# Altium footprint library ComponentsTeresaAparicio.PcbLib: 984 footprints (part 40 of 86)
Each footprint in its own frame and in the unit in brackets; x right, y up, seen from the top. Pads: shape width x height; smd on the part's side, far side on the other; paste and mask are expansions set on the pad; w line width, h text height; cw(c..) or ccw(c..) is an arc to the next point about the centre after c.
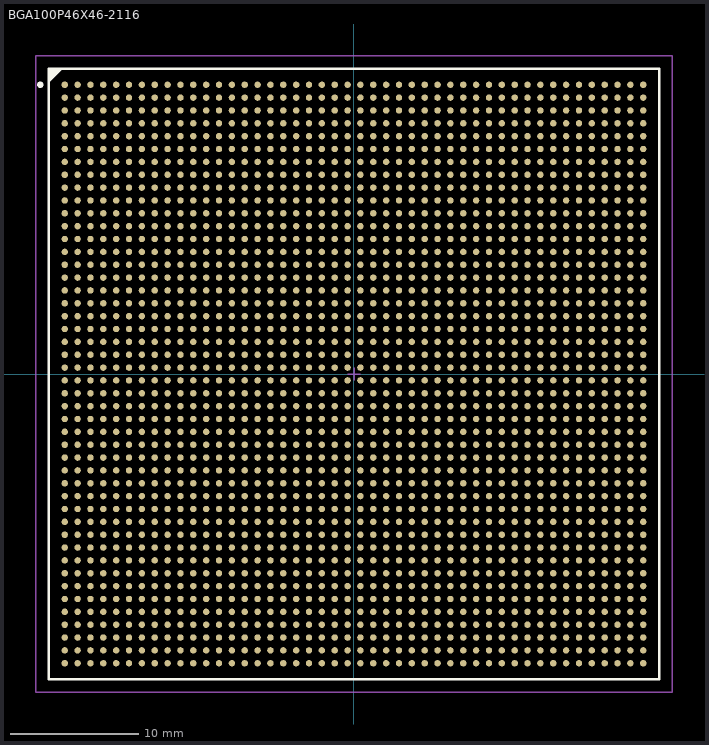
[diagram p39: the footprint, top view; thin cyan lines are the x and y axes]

## BGA100P46X46-2116 [mm] "BGA, 2116-Leads, Body 47.5x47.5mm, Pitch 1mm"
height 3.5
pads (2116):
  round 0.5 smd: A1(-22.5,22.5) A2(-21.5,22.5) A3(-20.5,22.5) A4(-19.5,22.5) A5(-18.5,22.5) A6(-17.5,22.5) A7(-16.5,22.5) A8(-15.5,22.5) A9(-14.5,22.5) A10(-13.5,22.5) A11(-12.5,22.5) A12(-11.5,22.5) A13(-10.5,22.5) A14(-9.5,22.5) A15(-8.5,22.5) A16(-7.5,22.5) A17(-6.5,22.5) A18(-5.5,22.5) A19(-4.5,22.5) A20(-3.5,22.5) A21(-2.5,22.5) A22(-1.5,22.5) A23(-0.5,22.5) A24(0.5,22.5) A25(1.5,22.5) A26(2.5,22.5) A27(3.5,22.5) A28(4.5,22.5) A29(5.5,22.5) A30(6.5,22.5) A31(7.5,22.5) A32(8.5,22.5) A33(9.5,22.5) A34(10.5,22.5) A35(11.5,22.5) A36(12.5,22.5) A37(13.5,22.5) A38(14.5,22.5) A39(15.5,22.5) A40(16.5,22.5) A41(17.5,22.5) A42(18.5,22.5) A43(19.5,22.5) A44(20.5,22.5) A45(21.5,22.5) A46(22.5,22.5) AA1(-22.5,2.5) AA2(-21.5,2.5) AA3(-20.5,2.5) AA4(-19.5,2.5) AA5(-18.5,2.5) AA6(-17.5,2.5) AA7(-16.5,2.5) AA8(-15.5,2.5) AA9(-14.5,2.5) AA10(-13.5,2.5) AA11(-12.5,2.5) AA12(-11.5,2.5) AA13(-10.5,2.5) AA14(-9.5,2.5) AA15(-8.5,2.5) AA16(-7.5,2.5) AA17(-6.5,2.5) AA18(-5.5,2.5) AA19(-4.5,2.5) AA20(-3.5,2.5) AA21(-2.5,2.5) AA22(-1.5,2.5) AA23(-0.5,2.5) AA24(0.5,2.5) AA25(1.5,2.5) AA26(2.5,2.5) AA27(3.5,2.5) AA28(4.5,2.5) AA29(5.5,2.5) AA30(6.5,2.5) AA31(7.5,2.5) AA32(8.5,2.5) AA33(9.5,2.5) AA34(10.5,2.5) AA35(11.5,2.5) AA36(12.5,2.5) AA37(13.5,2.5) AA38(14.5,2.5) AA39(15.5,2.5) AA40(16.5,2.5) AA41(17.5,2.5) AA42(18.5,2.5) AA43(19.5,2.5) AA44(20.5,2.5) AA45(21.5,2.5) AA46(22.5,2.5) AB1(-22.5,1.5) AB2(-21.5,1.5) AB3(-20.5,1.5) AB4(-19.5,1.5) AB5(-18.5,1.5) AB6(-17.5,1.5) AB7(-16.5,1.5) AB8(-15.5,1.5) AB9(-14.5,1.5) AB10(-13.5,1.5) AB11(-12.5,1.5) AB12(-11.5,1.5) AB13(-10.5,1.5) AB14(-9.5,1.5) AB15(-8.5,1.5) AB16(-7.5,1.5) AB17(-6.5,1.5) AB18(-5.5,1.5) AB19(-4.5,1.5) AB20(-3.5,1.5) AB21(-2.5,1.5) AB22(-1.5,1.5) AB23(-0.5,1.5) AB24(0.5,1.5) AB25(1.5,1.5) AB26(2.5,1.5) AB27(3.5,1.5) AB28(4.5,1.5) AB29(5.5,1.5) AB30(6.5,1.5) AB31(7.5,1.5) AB32(8.5,1.5) AB33(9.5,1.5) AB34(10.5,1.5) AB35(11.5,1.5) AB36(12.5,1.5) AB37(13.5,1.5) AB38(14.5,1.5) AB39(15.5,1.5) AB40(16.5,1.5) AB41(17.5,1.5) AB42(18.5,1.5) AB43(19.5,1.5) AB44(20.5,1.5) AB45(21.5,1.5) AB46(22.5,1.5) AC1(-22.5,0.5) AC2(-21.5,0.5) AC3(-20.5,0.5) AC4(-19.5,0.5) AC5(-18.5,0.5) AC6(-17.5,0.5) AC7(-16.5,0.5) AC8(-15.5,0.5) AC9(-14.5,0.5) AC10(-13.5,0.5) AC11(-12.5,0.5) AC12(-11.5,0.5) AC13(-10.5,0.5) AC14(-9.5,0.5) AC15(-8.5,0.5) AC16(-7.5,0.5) AC17(-6.5,0.5) AC18(-5.5,0.5) AC19(-4.5,0.5) AC20(-3.5,0.5) AC21(-2.5,0.5) AC22(-1.5,0.5) AC23(-0.5,0.5) AC24(0.5,0.5) AC25(1.5,0.5) AC26(2.5,0.5) AC27(3.5,0.5) AC28(4.5,0.5) AC29(5.5,0.5) AC30(6.5,0.5) AC31(7.5,0.5) AC32(8.5,0.5) AC33(9.5,0.5) AC34(10.5,0.5) AC35(11.5,0.5) AC36(12.5,0.5) AC37(13.5,0.5) AC38(14.5,0.5) AC39(15.5,0.5) AC40(16.5,0.5) AC41(17.5,0.5) AC42(18.5,0.5) AC43(19.5,0.5) AC44(20.5,0.5) AC45(21.5,0.5) AC46(22.5,0.5) AD1(-22.5,-0.5) AD2(-21.5,-0.5) AD3(-20.5,-0.5) AD4(-19.5,-0.5) AD5(-18.5,-0.5) AD6(-17.5,-0.5) AD7(-16.5,-0.5) AD8(-15.5,-0.5) AD9(-14.5,-0.5) AD10(-13.5,-0.5) AD11(-12.5,-0.5) AD12(-11.5,-0.5) AD13(-10.5,-0.5) AD14(-9.5,-0.5) AD15(-8.5,-0.5) AD16(-7.5,-0.5) AD17(-6.5,-0.5) AD18(-5.5,-0.5) AD19(-4.5,-0.5) AD20(-3.5,-0.5) AD21(-2.5,-0.5) AD22(-1.5,-0.5) AD23(-0.5,-0.5) AD24(0.5,-0.5) AD25(1.5,-0.5) AD26(2.5,-0.5) AD27(3.5,-0.5) AD28(4.5,-0.5) AD29(5.5,-0.5) AD30(6.5,-0.5) AD31(7.5,-0.5) AD32(8.5,-0.5) AD33(9.5,-0.5) AD34(10.5,-0.5) AD35(11.5,-0.5) AD36(12.5,-0.5) AD37(13.5,-0.5) AD38(14.5,-0.5) AD39(15.5,-0.5) AD40(16.5,-0.5) AD41(17.5,-0.5) AD42(18.5,-0.5) AD43(19.5,-0.5) AD44(20.5,-0.5) AD45(21.5,-0.5) AD46(22.5,-0.5) AE1(-22.5,-1.5) AE2(-21.5,-1.5) AE3(-20.5,-1.5) AE4(-19.5,-1.5) AE5(-18.5,-1.5) AE6(-17.5,-1.5) AE7(-16.5,-1.5) AE8(-15.5,-1.5) AE9(-14.5,-1.5) AE10(-13.5,-1.5) AE11(-12.5,-1.5) AE12(-11.5,-1.5) AE13(-10.5,-1.5) AE14(-9.5,-1.5) AE15(-8.5,-1.5) AE16(-7.5,-1.5) AE17(-6.5,-1.5) AE18(-5.5,-1.5) AE19(-4.5,-1.5) AE20(-3.5,-1.5) AE21(-2.5,-1.5) AE22(-1.5,-1.5) AE23(-0.5,-1.5) AE24(0.5,-1.5) AE25(1.5,-1.5) AE26(2.5,-1.5) AE27(3.5,-1.5) AE28(4.5,-1.5) AE29(5.5,-1.5) AE30(6.5,-1.5) AE31(7.5,-1.5) AE32(8.5,-1.5) AE33(9.5,-1.5) AE34(10.5,-1.5) AE35(11.5,-1.5) AE36(12.5,-1.5) AE37(13.5,-1.5) AE38(14.5,-1.5) AE39(15.5,-1.5) AE40(16.5,-1.5) AE41(17.5,-1.5) AE42(18.5,-1.5) AE43(19.5,-1.5) AE44(20.5,-1.5) AE45(21.5,-1.5) AE46(22.5,-1.5) AF1(-22.5,-2.5) AF2(-21.5,-2.5) AF3(-20.5,-2.5) AF4(-19.5,-2.5) AF5(-18.5,-2.5) AF6(-17.5,-2.5) AF7(-16.5,-2.5) AF8(-15.5,-2.5) AF9(-14.5,-2.5) AF10(-13.5,-2.5) AF11(-12.5,-2.5) AF12(-11.5,-2.5) AF13(-10.5,-2.5) AF14(-9.5,-2.5) AF15(-8.5,-2.5) AF16(-7.5,-2.5) AF17(-6.5,-2.5) AF18(-5.5,-2.5) AF19(-4.5,-2.5) AF20(-3.5,-2.5) AF21(-2.5,-2.5) AF22(-1.5,-2.5) AF23(-0.5,-2.5) AF24(0.5,-2.5) AF25(1.5,-2.5) AF26(2.5,-2.5) AF27(3.5,-2.5) AF28(4.5,-2.5) AF29(5.5,-2.5) AF30(6.5,-2.5) AF31(7.5,-2.5) AF32(8.5,-2.5) AF33(9.5,-2.5) AF34(10.5,-2.5) AF35(11.5,-2.5) AF36(12.5,-2.5) AF37(13.5,-2.5) AF38(14.5,-2.5) AF39(15.5,-2.5) AF40(16.5,-2.5) AF41(17.5,-2.5) AF42(18.5,-2.5) AF43(19.5,-2.5) AF44(20.5,-2.5) AF45(21.5,-2.5) AF46(22.5,-2.5) AG1(-22.5,-3.5) AG2(-21.5,-3.5) AG3(-20.5,-3.5) AG4(-19.5,-3.5) AG5(-18.5,-3.5) AG6(-17.5,-3.5) AG7(-16.5,-3.5) AG8(-15.5,-3.5) AG9(-14.5,-3.5) AG10(-13.5,-3.5) AG11(-12.5,-3.5) AG12(-11.5,-3.5) AG13(-10.5,-3.5) AG14(-9.5,-3.5) AG15(-8.5,-3.5) AG16(-7.5,-3.5) AG17(-6.5,-3.5) AG18(-5.5,-3.5) AG19(-4.5,-3.5) AG20(-3.5,-3.5) AG21(-2.5,-3.5) AG22(-1.5,-3.5) AG23(-0.5,-3.5) AG24(0.5,-3.5) AG25(1.5,-3.5) AG26(2.5,-3.5) AG27(3.5,-3.5) AG28(4.5,-3.5) AG29(5.5,-3.5) AG30(6.5,-3.5) AG31(7.5,-3.5) AG32(8.5,-3.5) AG33(9.5,-3.5) AG34(10.5,-3.5) AG35(11.5,-3.5) AG36(12.5,-3.5) AG37(13.5,-3.5) AG38(14.5,-3.5) AG39(15.5,-3.5) AG40(16.5,-3.5) AG41(17.5,-3.5) AG42(18.5,-3.5) AG43(19.5,-3.5) AG44(20.5,-3.5) AG45(21.5,-3.5) AG46(22.5,-3.5) AH1(-22.5,-4.5) AH2(-21.5,-4.5) AH3(-20.5,-4.5) AH4(-19.5,-4.5) AH5(-18.5,-4.5) AH6(-17.5,-4.5) AH7(-16.5,-4.5) AH8(-15.5,-4.5) AH9(-14.5,-4.5) AH10(-13.5,-4.5) AH11(-12.5,-4.5) AH12(-11.5,-4.5) AH13(-10.5,-4.5) AH14(-9.5,-4.5) AH15(-8.5,-4.5) AH16(-7.5,-4.5) AH17(-6.5,-4.5) AH18(-5.5,-4.5) AH19(-4.5,-4.5) AH20(-3.5,-4.5) AH21(-2.5,-4.5) AH22(-1.5,-4.5) AH23(-0.5,-4.5) AH24(0.5,-4.5) AH25(1.5,-4.5) AH26(2.5,-4.5) AH27(3.5,-4.5) AH28(4.5,-4.5) AH29(5.5,-4.5) AH30(6.5,-4.5) AH31(7.5,-4.5) AH32(8.5,-4.5) AH33(9.5,-4.5) AH34(10.5,-4.5) AH35(11.5,-4.5) AH36(12.5,-4.5) AH37(13.5,-4.5) AH38(14.5,-4.5) AH39(15.5,-4.5) AH40(16.5,-4.5) AH41(17.5,-4.5) AH42(18.5,-4.5) AH43(19.5,-4.5) AH44(20.5,-4.5) AH45(21.5,-4.5) AH46(22.5,-4.5) AJ1(-22.5,-5.5) AJ2(-21.5,-5.5) AJ3(-20.5,-5.5) AJ4(-19.5,-5.5) AJ5(-18.5,-5.5) AJ6(-17.5,-5.5) AJ7(-16.5,-5.5) AJ8(-15.5,-5.5) AJ9(-14.5,-5.5) AJ10(-13.5,-5.5) AJ11(-12.5,-5.5) AJ12(-11.5,-5.5) AJ13(-10.5,-5.5) AJ14(-9.5,-5.5) AJ15(-8.5,-5.5) AJ16(-7.5,-5.5) AJ17(-6.5,-5.5) AJ18(-5.5,-5.5) AJ19(-4.5,-5.5) AJ20(-3.5,-5.5) AJ21(-2.5,-5.5) AJ22(-1.5,-5.5) AJ23(-0.5,-5.5) AJ24(0.5,-5.5) AJ25(1.5,-5.5) AJ26(2.5,-5.5) AJ27(3.5,-5.5) AJ28(4.5,-5.5) AJ29(5.5,-5.5) AJ30(6.5,-5.5) AJ31(7.5,-5.5) AJ32(8.5,-5.5) AJ33(9.5,-5.5) AJ34(10.5,-5.5) AJ35(11.5,-5.5) AJ36(12.5,-5.5) AJ37(13.5,-5.5) AJ38(14.5,-5.5) AJ39(15.5,-5.5) AJ40(16.5,-5.5) AJ41(17.5,-5.5) AJ42(18.5,-5.5) AJ43(19.5,-5.5) AJ44(20.5,-5.5) AJ45(21.5,-5.5) AJ46(22.5,-5.5) AK1(-22.5,-6.5) AK2(-21.5,-6.5) AK3(-20.5,-6.5) AK4(-19.5,-6.5) AK5(-18.5,-6.5) AK6(-17.5,-6.5) AK7(-16.5,-6.5) AK8(-15.5,-6.5) AK9(-14.5,-6.5) AK10(-13.5,-6.5) AK11(-12.5,-6.5) AK12(-11.5,-6.5) AK13(-10.5,-6.5) AK14(-9.5,-6.5) AK15(-8.5,-6.5) AK16(-7.5,-6.5) AK17(-6.5,-6.5) AK18(-5.5,-6.5) AK19(-4.5,-6.5) AK20(-3.5,-6.5) AK21(-2.5,-6.5) AK22(-1.5,-6.5) AK23(-0.5,-6.5) AK24(0.5,-6.5) AK25(1.5,-6.5) AK26(2.5,-6.5) AK27(3.5,-6.5) AK28(4.5,-6.5) AK29(5.5,-6.5) AK30(6.5,-6.5) AK31(7.5,-6.5) AK32(8.5,-6.5) AK33(9.5,-6.5) AK34(10.5,-6.5) AK35(11.5,-6.5) AK36(12.5,-6.5) AK37(13.5,-6.5) AK38(14.5,-6.5) AK39(15.5,-6.5) AK40(16.5,-6.5) AK41(17.5,-6.5) AK42(18.5,-6.5) AK43(19.5,-6.5) AK44(20.5,-6.5) AK45(21.5,-6.5) AK46(22.5,-6.5) AL1(-22.5,-7.5) AL2(-21.5,-7.5) AL3(-20.5,-7.5) AL4(-19.5,-7.5) AL5(-18.5,-7.5) AL6(-17.5,-7.5) AL7(-16.5,-7.5) AL8(-15.5,-7.5) AL9(-14.5,-7.5) AL10(-13.5,-7.5) AL11(-12.5,-7.5) AL12(-11.5,-7.5) AL13(-10.5,-7.5) AL14(-9.5,-7.5) AL15(-8.5,-7.5) AL16(-7.5,-7.5) AL17(-6.5,-7.5) AL18(-5.5,-7.5) AL19(-4.5,-7.5) AL20(-3.5,-7.5) AL21(-2.5,-7.5) AL22(-1.5,-7.5) AL23(-0.5,-7.5) AL24(0.5,-7.5) AL25(1.5,-7.5) AL26(2.5,-7.5) AL27(3.5,-7.5) AL28(4.5,-7.5) AL29(5.5,-7.5) AL30(6.5,-7.5) AL31(7.5,-7.5) AL32(8.5,-7.5) AL33(9.5,-7.5) AL34(10.5,-7.5) AL35(11.5,-7.5) AL36(12.5,-7.5) AL37(13.5,-7.5) AL38(14.5,-7.5) AL39(15.5,-7.5) AL40(16.5,-7.5) AL41(17.5,-7.5) AL42(18.5,-7.5) AL43(19.5,-7.5) AL44(20.5,-7.5) AL45(21.5,-7.5) AL46(22.5,-7.5) AM1(-22.5,-8.5) AM2(-21.5,-8.5) AM3(-20.5,-8.5) AM4(-19.5,-8.5) AM5(-18.5,-8.5) AM6(-17.5,-8.5) AM7(-16.5,-8.5) AM8(-15.5,-8.5) AM9(-14.5,-8.5) AM10(-13.5,-8.5) AM11(-12.5,-8.5) AM12(-11.5,-8.5) AM13(-10.5,-8.5) AM14(-9.5,-8.5) AM15(-8.5,-8.5) AM16(-7.5,-8.5) AM17(-6.5,-8.5) AM18(-5.5,-8.5) AM19(-4.5,-8.5) AM20(-3.5,-8.5) AM21(-2.5,-8.5) AM22(-1.5,-8.5) AM23(-0.5,-8.5) AM24(0.5,-8.5) AM25(1.5,-8.5) AM26(2.5,-8.5) AM27(3.5,-8.5) AM28(4.5,-8.5) AM29(5.5,-8.5) AM30(6.5,-8.5) AM31(7.5,-8.5) AM32(8.5,-8.5) AM33(9.5,-8.5) AM34(10.5,-8.5) AM35(11.5,-8.5) AM36(12.5,-8.5) AM37(13.5,-8.5) AM38(14.5,-8.5) AM39(15.5,-8.5) AM40(16.5,-8.5) AM41(17.5,-8.5) AM42(18.5,-8.5) AM43(19.5,-8.5) AM44(20.5,-8.5) AM45(21.5,-8.5) AM46(22.5,-8.5) AN1(-22.5,-9.5) AN2(-21.5,-9.5) AN3(-20.5,-9.5) AN4(-19.5,-9.5) AN5(-18.5,-9.5) AN6(-17.5,-9.5) AN7(-16.5,-9.5) AN8(-15.5,-9.5) AN9(-14.5,-9.5) AN10(-13.5,-9.5) AN11(-12.5,-9.5) AN12(-11.5,-9.5) AN13(-10.5,-9.5) AN14(-9.5,-9.5) AN15(-8.5,-9.5) AN16(-7.5,-9.5) AN17(-6.5,-9.5) AN18(-5.5,-9.5) AN19(-4.5,-9.5) AN20(-3.5,-9.5) AN21(-2.5,-9.5) AN22(-1.5,-9.5) AN23(-0.5,-9.5) AN24(0.5,-9.5) AN25(1.5,-9.5) AN26(2.5,-9.5) AN27(3.5,-9.5) AN28(4.5,-9.5) AN29(5.5,-9.5) AN30(6.5,-9.5) AN31(7.5,-9.5) AN32(8.5,-9.5) AN33(9.5,-9.5) AN34(10.5,-9.5) AN35(11.5,-9.5) AN36(12.5,-9.5) AN37(13.5,-9.5) AN38(14.5,-9.5) AN39(15.5,-9.5) AN40(16.5,-9.5) AN41(17.5,-9.5) AN42(18.5,-9.5) AN43(19.5,-9.5) AN44(20.5,-9.5) AN45(21.5,-9.5) AN46(22.5,-9.5) AP1(-22.5,-10.5) AP2(-21.5,-10.5) AP3(-20.5,-10.5) AP4(-19.5,-10.5) AP5(-18.5,-10.5) AP6(-17.5,-10.5) AP7(-16.5,-10.5) AP8(-15.5,-10.5) AP9(-14.5,-10.5) AP10(-13.5,-10.5) AP11(-12.5,-10.5) AP12(-11.5,-10.5) AP13(-10.5,-10.5) AP14(-9.5,-10.5) AP15(-8.5,-10.5) AP16(-7.5,-10.5) AP17(-6.5,-10.5) AP18(-5.5,-10.5) AP19(-4.5,-10.5) AP20(-3.5,-10.5) AP21(-2.5,-10.5) AP22(-1.5,-10.5) AP23(-0.5,-10.5) AP24(0.5,-10.5) AP25(1.5,-10.5) AP26(2.5,-10.5) AP27(3.5,-10.5) AP28(4.5,-10.5) AP29(5.5,-10.5) AP30(6.5,-10.5) AP31(7.5,-10.5) AP32(8.5,-10.5) AP33(9.5,-10.5) AP34(10.5,-10.5) AP35(11.5,-10.5) AP36(12.5,-10.5) AP37(13.5,-10.5) AP38(14.5,-10.5) AP39(15.5,-10.5) AP40(16.5,-10.5) AP41(17.5,-10.5) AP42(18.5,-10.5) AP43(19.5,-10.5) AP44(20.5,-10.5) AP45(21.5,-10.5) AP46(22.5,-10.5) AR1(-22.5,-11.5) AR2(-21.5,-11.5) AR3(-20.5,-11.5) AR4(-19.5,-11.5) AR5(-18.5,-11.5) AR6(-17.5,-11.5) AR7(-16.5,-11.5) AR8(-15.5,-11.5) AR9(-14.5,-11.5) AR10(-13.5,-11.5) AR11(-12.5,-11.5) AR12(-11.5,-11.5) AR13(-10.5,-11.5) AR14(-9.5,-11.5) AR15(-8.5,-11.5) AR16(-7.5,-11.5) AR17(-6.5,-11.5) AR18(-5.5,-11.5) AR19(-4.5,-11.5) AR20(-3.5,-11.5) AR21(-2.5,-11.5) AR22(-1.5,-11.5) AR23(-0.5,-11.5) AR24(0.5,-11.5) AR25(1.5,-11.5) AR26(2.5,-11.5) AR27(3.5,-11.5) AR28(4.5,-11.5) AR29(5.5,-11.5) AR30(6.5,-11.5) AR31(7.5,-11.5) AR32(8.5,-11.5) AR33(9.5,-11.5) AR34(10.5,-11.5) AR35(11.5,-11.5) AR36(12.5,-11.5) AR37(13.5,-11.5) AR38(14.5,-11.5) AR39(15.5,-11.5) AR40(16.5,-11.5) AR41(17.5,-11.5) AR42(18.5,-11.5) AR43(19.5,-11.5) AR44(20.5,-11.5) AR45(21.5,-11.5) AR46(22.5,-11.5) AT1(-22.5,-12.5) AT2(-21.5,-12.5) AT3(-20.5,-12.5) AT4(-19.5,-12.5) AT5(-18.5,-12.5) AT6(-17.5,-12.5) AT7(-16.5,-12.5) AT8(-15.5,-12.5) AT9(-14.5,-12.5) AT10(-13.5,-12.5) AT11(-12.5,-12.5) AT12(-11.5,-12.5) AT13(-10.5,-12.5) AT14(-9.5,-12.5) AT15(-8.5,-12.5) AT16(-7.5,-12.5) AT17(-6.5,-12.5) AT18(-5.5,-12.5) AT19(-4.5,-12.5) AT20(-3.5,-12.5) AT21(-2.5,-12.5) AT22(-1.5,-12.5) AT23(-0.5,-12.5) AT24(0.5,-12.5) AT25(1.5,-12.5) AT26(2.5,-12.5) AT27(3.5,-12.5) AT28(4.5,-12.5) AT29(5.5,-12.5) AT30(6.5,-12.5) AT31(7.5,-12.5) AT32(8.5,-12.5) AT33(9.5,-12.5) AT34(10.5,-12.5) AT35(11.5,-12.5) AT36(12.5,-12.5) AT37(13.5,-12.5) AT38(14.5,-12.5) AT39(15.5,-12.5) AT40(16.5,-12.5) AT41(17.5,-12.5) AT42(18.5,-12.5) AT43(19.5,-12.5) AT44(20.5,-12.5) AT45(21.5,-12.5) AT46(22.5,-12.5) AU1(-22.5,-13.5) AU2(-21.5,-13.5) AU3(-20.5,-13.5) AU4(-19.5,-13.5) AU5(-18.5,-13.5) AU6(-17.5,-13.5) AU7(-16.5,-13.5) AU8(-15.5,-13.5) AU9(-14.5,-13.5) AU10(-13.5,-13.5) AU11(-12.5,-13.5) AU12(-11.5,-13.5) AU13(-10.5,-13.5) AU14(-9.5,-13.5) AU15(-8.5,-13.5) AU16(-7.5,-13.5) AU17(-6.5,-13.5) AU18(-5.5,-13.5) AU19(-4.5,-13.5) AU20(-3.5,-13.5) AU21(-2.5,-13.5) AU22(-1.5,-13.5) AU23(-0.5,-13.5) AU24(0.5,-13.5) AU25(1.5,-13.5) AU26(2.5,-13.5) AU27(3.5,-13.5) AU28(4.5,-13.5) AU29(5.5,-13.5) AU30(6.5,-13.5) AU31(7.5,-13.5) AU32(8.5,-13.5) AU33(9.5,-13.5) AU34(10.5,-13.5) AU35(11.5,-13.5) AU36(12.5,-13.5) AU37(13.5,-13.5) AU38(14.5,-13.5) AU39(15.5,-13.5) AU40(16.5,-13.5) AU41(17.5,-13.5) AU42(18.5,-13.5) AU43(19.5,-13.5) AU44(20.5,-13.5) AU45(21.5,-13.5) AU46(22.5,-13.5) AV1(-22.5,-14.5) AV2(-21.5,-14.5) AV3(-20.5,-14.5) AV4(-19.5,-14.5) AV5(-18.5,-14.5) AV6(-17.5,-14.5) AV7(-16.5,-14.5) AV8(-15.5,-14.5) AV9(-14.5,-14.5) AV10(-13.5,-14.5) AV11(-12.5,-14.5) AV12(-11.5,-14.5) AV13(-10.5,-14.5) AV14(-9.5,-14.5) AV15(-8.5,-14.5) AV16(-7.5,-14.5) AV17(-6.5,-14.5) AV18(-5.5,-14.5) AV19(-4.5,-14.5) AV20(-3.5,-14.5) AV21(-2.5,-14.5) AV22(-1.5,-14.5) AV23(-0.5,-14.5) AV24(0.5,-14.5) AV25(1.5,-14.5) AV26(2.5,-14.5) AV27(3.5,-14.5) AV28(4.5,-14.5) AV29(5.5,-14.5) AV30(6.5,-14.5) AV31(7.5,-14.5) AV32(8.5,-14.5) AV33(9.5,-14.5) AV34(10.5,-14.5) AV35(11.5,-14.5) AV36(12.5,-14.5) AV37(13.5,-14.5) AV38(14.5,-14.5) AV39(15.5,-14.5) AV40(16.5,-14.5) AV41(17.5,-14.5) AV42(18.5,-14.5) AV43(19.5,-14.5) AV44(20.5,-14.5) AV45(21.5,-14.5) AV46(22.5,-14.5) AW1(-22.5,-15.5) AW2(-21.5,-15.5) AW3(-20.5,-15.5) AW4(-19.5,-15.5) AW5(-18.5,-15.5) AW6(-17.5,-15.5) AW7(-16.5,-15.5) AW8(-15.5,-15.5) AW9(-14.5,-15.5) AW10(-13.5,-15.5) AW11(-12.5,-15.5) AW12(-11.5,-15.5) AW13(-10.5,-15.5) AW14(-9.5,-15.5) AW15(-8.5,-15.5) AW16(-7.5,-15.5) AW17(-6.5,-15.5) AW18(-5.5,-15.5) AW19(-4.5,-15.5) AW20(-3.5,-15.5) AW21(-2.5,-15.5) AW22(-1.5,-15.5) AW23(-0.5,-15.5) AW24(0.5,-15.5) AW25(1.5,-15.5) AW26(2.5,-15.5) AW27(3.5,-15.5) AW28(4.5,-15.5) AW29(5.5,-15.5) AW30(6.5,-15.5) AW31(7.5,-15.5) AW32(8.5,-15.5) AW33(9.5,-15.5) AW34(10.5,-15.5) AW35(11.5,-15.5) AW36(12.5,-15.5) AW37(13.5,-15.5) AW38(14.5,-15.5) AW39(15.5,-15.5) AW40(16.5,-15.5) AW41(17.5,-15.5) AW42(18.5,-15.5) AW43(19.5,-15.5) AW44(20.5,-15.5) AW45(21.5,-15.5) AW46(22.5,-15.5) AY1(-22.5,-16.5) AY2(-21.5,-16.5) AY3(-20.5,-16.5) AY4(-19.5,-16.5) AY5(-18.5,-16.5) AY6(-17.5,-16.5) AY7(-16.5,-16.5) AY8(-15.5,-16.5) AY9(-14.5,-16.5) AY10(-13.5,-16.5) AY11(-12.5,-16.5) AY12(-11.5,-16.5) AY13(-10.5,-16.5) AY14(-9.5,-16.5) AY15(-8.5,-16.5) AY16(-7.5,-16.5) AY17(-6.5,-16.5) AY18(-5.5,-16.5) AY19(-4.5,-16.5) AY20(-3.5,-16.5) AY21(-2.5,-16.5) AY22(-1.5,-16.5) AY23(-0.5,-16.5) AY24(0.5,-16.5) AY25(1.5,-16.5) AY26(2.5,-16.5) AY27(3.5,-16.5) AY28(4.5,-16.5) AY29(5.5,-16.5) AY30(6.5,-16.5) AY31(7.5,-16.5) AY32(8.5,-16.5) AY33(9.5,-16.5) AY34(10.5,-16.5) AY35(11.5,-16.5) AY36(12.5,-16.5) AY37(13.5,-16.5) AY38(14.5,-16.5) AY39(15.5,-16.5) AY40(16.5,-16.5) AY41(17.5,-16.5) AY42(18.5,-16.5) AY43(19.5,-16.5) AY44(20.5,-16.5) AY45(21.5,-16.5) AY46(22.5,-16.5) B1(-22.5,21.5) B2(-21.5,21.5) B3(-20.5,21.5) B4(-19.5,21.5) B5(-18.5,21.5) B6(-17.5,21.5) B7(-16.5,21.5) B8(-15.5,21.5) B9(-14.5,21.5) B10(-13.5,21.5) B11(-12.5,21.5) B12(-11.5,21.5) B13(-10.5,21.5) B14(-9.5,21.5) B15(-8.5,21.5) B16(-7.5,21.5) B17(-6.5,21.5) B18(-5.5,21.5) B19(-4.5,21.5) B20(-3.5,21.5) B21(-2.5,21.5) B22(-1.5,21.5) B23(-0.5,21.5) B24(0.5,21.5) B25(1.5,21.5) B26(2.5,21.5) B27(3.5,21.5) B28(4.5,21.5) B29(5.5,21.5) B30(6.5,21.5) B31(7.5,21.5) B32(8.5,21.5) B33(9.5,21.5) B34(10.5,21.5) B35(11.5,21.5) B36(12.5,21.5) B37(13.5,21.5) B38(14.5,21.5) B39(15.5,21.5) B40(16.5,21.5) B41(17.5,21.5) B42(18.5,21.5) B43(19.5,21.5) B44(20.5,21.5) B45(21.5,21.5) B46(22.5,21.5) BA1(-22.5,-17.5) BA2(-21.5,-17.5) BA3(-20.5,-17.5) BA4(-19.5,-17.5) BA5(-18.5,-17.5) BA6(-17.5,-17.5) BA7(-16.5,-17.5) BA8(-15.5,-17.5) BA9(-14.5,-17.5) BA10(-13.5,-17.5) BA11(-12.5,-17.5) BA12(-11.5,-17.5) BA13(-10.5,-17.5) BA14(-9.5,-17.5) BA15(-8.5,-17.5) BA16(-7.5,-17.5) BA17(-6.5,-17.5) BA18(-5.5,-17.5) BA19(-4.5,-17.5) BA20(-3.5,-17.5) BA21(-2.5,-17.5) BA22(-1.5,-17.5) BA23(-0.5,-17.5) BA24(0.5,-17.5) BA25(1.5,-17.5) BA26(2.5,-17.5) BA27(3.5,-17.5) BA28(4.5,-17.5) BA29(5.5,-17.5) BA30(6.5,-17.5) BA31(7.5,-17.5) BA32(8.5,-17.5) BA33(9.5,-17.5) BA34(10.5,-17.5) BA35(11.5,-17.5) BA36(12.5,-17.5) BA37(13.5,-17.5) BA38(14.5,-17.5) BA39(15.5,-17.5) BA40(16.5,-17.5) BA41(17.5,-17.5) BA42(18.5,-17.5) BA43(19.5,-17.5) BA44(20.5,-17.5) BA45(21.5,-17.5) BA46(22.5,-17.5) BB1(-22.5,-18.5) BB2(-21.5,-18.5) BB3(-20.5,-18.5) BB4(-19.5,-18.5) BB5(-18.5,-18.5) BB6(-17.5,-18.5) BB7(-16.5,-18.5) BB8(-15.5,-18.5) BB9(-14.5,-18.5) BB10(-13.5,-18.5) BB11(-12.5,-18.5) BB12(-11.5,-18.5) BB13(-10.5,-18.5) BB14(-9.5,-18.5) BB15(-8.5,-18.5) BB16(-7.5,-18.5) BB17(-6.5,-18.5) BB18(-5.5,-18.5) BB19(-4.5,-18.5) BB20(-3.5,-18.5) BB21(-2.5,-18.5) BB22(-1.5,-18.5) BB23(-0.5,-18.5) BB24(0.5,-18.5) BB25(1.5,-18.5) BB26(2.5,-18.5) BB27(3.5,-18.5) BB28(4.5,-18.5) BB29(5.5,-18.5) BB30(6.5,-18.5) BB31(7.5,-18.5) BB32(8.5,-18.5) BB33(9.5,-18.5) BB34(10.5,-18.5) BB35(11.5,-18.5) BB36(12.5,-18.5) BB37(13.5,-18.5) BB38(14.5,-18.5) BB39(15.5,-18.5) BB40(16.5,-18.5) BB41(17.5,-18.5) BB42(18.5,-18.5) BB43(19.5,-18.5) BB44(20.5,-18.5) BB45(21.5,-18.5) BB46(22.5,-18.5) BC1(-22.5,-19.5) BC2(-21.5,-19.5) BC3(-20.5,-19.5) BC4(-19.5,-19.5) BC5(-18.5,-19.5) BC6(-17.5,-19.5) BC7(-16.5,-19.5) BC8(-15.5,-19.5) BC9(-14.5,-19.5) BC10(-13.5,-19.5) BC11(-12.5,-19.5) BC12(-11.5,-19.5) BC13(-10.5,-19.5) BC14(-9.5,-19.5) BC15(-8.5,-19.5) BC16(-7.5,-19.5) BC17(-6.5,-19.5) BC18(-5.5,-19.5) BC19(-4.5,-19.5) BC20(-3.5,-19.5) BC21(-2.5,-19.5) BC22(-1.5,-19.5) BC23(-0.5,-19.5) BC24(0.5,-19.5) BC25(1.5,-19.5) BC26(2.5,-19.5) BC27(3.5,-19.5) BC28(4.5,-19.5) BC29(5.5,-19.5) BC30(6.5,-19.5) BC31(7.5,-19.5) BC32(8.5,-19.5) BC33(9.5,-19.5) BC34(10.5,-19.5) BC35(11.5,-19.5) BC36(12.5,-19.5) BC37(13.5,-19.5) BC38(14.5,-19.5) BC39(15.5,-19.5) BC40(16.5,-19.5) BC41(17.5,-19.5) BC42(18.5,-19.5) BC43(19.5,-19.5) BC44(20.5,-19.5) BC45(21.5,-19.5) BC46(22.5,-19.5) BD1(-22.5,-20.5) BD2(-21.5,-20.5) BD3(-20.5,-20.5) BD4(-19.5,-20.5) BD5(-18.5,-20.5) BD6(-17.5,-20.5) BD7(-16.5,-20.5) BD8(-15.5,-20.5) BD9(-14.5,-20.5) BD10(-13.5,-20.5) BD11(-12.5,-20.5) BD12(-11.5,-20.5) BD13(-10.5,-20.5) BD14(-9.5,-20.5) BD15(-8.5,-20.5) BD16(-7.5,-20.5) BD17(-6.5,-20.5) BD18(-5.5,-20.5) BD19(-4.5,-20.5) BD20(-3.5,-20.5) BD21(-2.5,-20.5) BD22(-1.5,-20.5) BD23(-0.5,-20.5) BD24(0.5,-20.5) BD25(1.5,-20.5) BD26(2.5,-20.5) BD27(3.5,-20.5) BD28(4.5,-20.5) BD29(5.5,-20.5) BD30(6.5,-20.5) BD31(7.5,-20.5) BD32(8.5,-20.5) BD33(9.5,-20.5) BD34(10.5,-20.5) BD35(11.5,-20.5) BD36(12.5,-20.5) BD37(13.5,-20.5) BD38(14.5,-20.5) BD39(15.5,-20.5) BD40(16.5,-20.5) BD41(17.5,-20.5) BD42(18.5,-20.5) BD43(19.5,-20.5) BD44(20.5,-20.5) BD45(21.5,-20.5) BD46(22.5,-20.5) BE1(-22.5,-21.5) BE2(-21.5,-21.5) BE3(-20.5,-21.5) BE4(-19.5,-21.5) BE5(-18.5,-21.5) BE6(-17.5,-21.5) BE7(-16.5,-21.5) BE8(-15.5,-21.5) BE9(-14.5,-21.5) BE10(-13.5,-21.5) BE11(-12.5,-21.5) BE12(-11.5,-21.5) BE13(-10.5,-21.5) BE14(-9.5,-21.5) BE15(-8.5,-21.5) BE16(-7.5,-21.5) BE17(-6.5,-21.5) BE18(-5.5,-21.5) BE19(-4.5,-21.5) BE20(-3.5,-21.5) BE21(-2.5,-21.5) BE22(-1.5,-21.5) BE23(-0.5,-21.5) BE24(0.5,-21.5) BE25(1.5,-21.5) BE26(2.5,-21.5) BE27(3.5,-21.5) BE28(4.5,-21.5) BE29(5.5,-21.5) BE30(6.5,-21.5) BE31(7.5,-21.5) BE32(8.5,-21.5) BE33(9.5,-21.5) BE34(10.5,-21.5) BE35(11.5,-21.5) BE36(12.5,-21.5) BE37(13.5,-21.5) BE38(14.5,-21.5) BE39(15.5,-21.5) BE40(16.5,-21.5) BE41(17.5,-21.5) BE42(18.5,-21.5) BE43(19.5,-21.5) BE44(20.5,-21.5) BE45(21.5,-21.5) BE46(22.5,-21.5) BF1(-22.5,-22.5) BF2(-21.5,-22.5) BF3(-20.5,-22.5) BF4(-19.5,-22.5) BF5(-18.5,-22.5) BF6(-17.5,-22.5) BF7(-16.5,-22.5) BF8(-15.5,-22.5) BF9(-14.5,-22.5) BF10(-13.5,-22.5) BF11(-12.5,-22.5) BF12(-11.5,-22.5) BF13(-10.5,-22.5) BF14(-9.5,-22.5) BF15(-8.5,-22.5) BF16(-7.5,-22.5) BF17(-6.5,-22.5) BF18(-5.5,-22.5) BF19(-4.5,-22.5) BF20(-3.5,-22.5) BF21(-2.5,-22.5) BF22(-1.5,-22.5) BF23(-0.5,-22.5) BF24(0.5,-22.5) BF25(1.5,-22.5) BF26(2.5,-22.5) BF27(3.5,-22.5) BF28(4.5,-22.5) BF29(5.5,-22.5) BF30(6.5,-22.5) BF31(7.5,-22.5) BF32(8.5,-22.5) BF33(9.5,-22.5) BF34(10.5,-22.5) BF35(11.5,-22.5) BF36(12.5,-22.5) BF37(13.5,-22.5) BF38(14.5,-22.5) BF39(15.5,-22.5) BF40(16.5,-22.5) BF41(17.5,-22.5) BF42(18.5,-22.5) BF43(19.5,-22.5) BF44(20.5,-22.5) BF45(21.5,-22.5) BF46(22.5,-22.5) C1(-22.5,20.5) C2(-21.5,20.5) C3(-20.5,20.5) C4(-19.5,20.5) C5(-18.5,20.5) C6(-17.5,20.5) C7(-16.5,20.5) C8(-15.5,20.5) C9(-14.5,20.5) C10(-13.5,20.5) C11(-12.5,20.5) C12(-11.5,20.5) C13(-10.5,20.5) C14(-9.5,20.5) C15(-8.5,20.5) C16(-7.5,20.5) C17(-6.5,20.5) C18(-5.5,20.5) C19(-4.5,20.5) C20(-3.5,20.5) C21(-2.5,20.5) C22(-1.5,20.5) C23(-0.5,20.5) C24(0.5,20.5) C25(1.5,20.5) C26(2.5,20.5) C27(3.5,20.5) C28(4.5,20.5) C29(5.5,20.5) C30(6.5,20.5) C31(7.5,20.5) C32(8.5,20.5) C33(9.5,20.5) C34(10.5,20.5) C35(11.5,20.5) C36(12.5,20.5) C37(13.5,20.5) C38(14.5,20.5) C39(15.5,20.5) C40(16.5,20.5) C41(17.5,20.5) C42(18.5,20.5) C43(19.5,20.5) C44(20.5,20.5) C45(21.5,20.5) C46(22.5,20.5) D1(-22.5,19.5) D2(-21.5,19.5) D3(-20.5,19.5) D4(-19.5,19.5) D5(-18.5,19.5) D6(-17.5,19.5) D7(-16.5,19.5) D8(-15.5,19.5) D9(-14.5,19.5) D10(-13.5,19.5) D11(-12.5,19.5) D12(-11.5,19.5) D13(-10.5,19.5) D14(-9.5,19.5) D15(-8.5,19.5) D16(-7.5,19.5) D17(-6.5,19.5) D18(-5.5,19.5) D19(-4.5,19.5) D20(-3.5,19.5) D21(-2.5,19.5) D22(-1.5,19.5) D23(-0.5,19.5) D24(0.5,19.5) D25(1.5,19.5) D26(2.5,19.5) D27(3.5,19.5) D28(4.5,19.5) D29(5.5,19.5) D30(6.5,19.5) D31(7.5,19.5) D32(8.5,19.5) D33(9.5,19.5) D34(10.5,19.5) D35(11.5,19.5) D36(12.5,19.5) D37(13.5,19.5) D38(14.5,19.5) D39(15.5,19.5) D40(16.5,19.5) D41(17.5,19.5) D42(18.5,19.5) D43(19.5,19.5) D44(20.5,19.5) D45(21.5,19.5) D46(22.5,19.5) E1(-22.5,18.5) E2(-21.5,18.5) E3(-20.5,18.5) E4(-19.5,18.5) E5(-18.5,18.5) E6(-17.5,18.5) E7(-16.5,18.5) E8(-15.5,18.5) E9(-14.5,18.5) E10(-13.5,18.5) E11(-12.5,18.5) E12(-11.5,18.5) E13(-10.5,18.5) E14(-9.5,18.5) E15(-8.5,18.5) E16(-7.5,18.5) E17(-6.5,18.5) E18(-5.5,18.5) E19(-4.5,18.5) E20(-3.5,18.5) E21(-2.5,18.5) E22(-1.5,18.5) E23(-0.5,18.5) E24(0.5,18.5) E25(1.5,18.5) E26(2.5,18.5) E27(3.5,18.5) E28(4.5,18.5) E29(5.5,18.5) E30(6.5,18.5) E31(7.5,18.5) E32(8.5,18.5) E33(9.5,18.5) E34(10.5,18.5) E35(11.5,18.5) E36(12.5,18.5) E37(13.5,18.5) E38(14.5,18.5) E39(15.5,18.5) E40(16.5,18.5) E41(17.5,18.5) E42(18.5,18.5) E43(19.5,18.5) E44(20.5,18.5) E45(21.5,18.5) E46(22.5,18.5) F1(-22.5,17.5) F2(-21.5,17.5) F3(-20.5,17.5) F4(-19.5,17.5) F5(-18.5,17.5) F6(-17.5,17.5) F7(-16.5,17.5) F8(-15.5,17.5) F9(-14.5,17.5) F10(-13.5,17.5) F11(-12.5,17.5) F12(-11.5,17.5) F13(-10.5,17.5) F14(-9.5,17.5) F15(-8.5,17.5) F16(-7.5,17.5) F17(-6.5,17.5) F18(-5.5,17.5) F19(-4.5,17.5) F20(-3.5,17.5) F21(-2.5,17.5) F22(-1.5,17.5) F23(-0.5,17.5) F24(0.5,17.5) F25(1.5,17.5) F26(2.5,17.5) F27(3.5,17.5) F28(4.5,17.5) F29(5.5,17.5) F30(6.5,17.5) F31(7.5,17.5) F32(8.5,17.5) F33(9.5,17.5) F34(10.5,17.5) F35(11.5,17.5) F36(12.5,17.5) F37(13.5,17.5) F38(14.5,17.5) F39(15.5,17.5) F40(16.5,17.5) F41(17.5,17.5) F42(18.5,17.5) F43(19.5,17.5) F44(20.5,17.5) F45(21.5,17.5) F46(22.5,17.5) G1(-22.5,16.5) G2(-21.5,16.5) G3(-20.5,16.5) G4(-19.5,16.5) G5(-18.5,16.5) G6(-17.5,16.5) G7(-16.5,16.5) G8(-15.5,16.5) G9(-14.5,16.5) G10(-13.5,16.5) G11(-12.5,16.5) G12(-11.5,16.5) G13(-10.5,16.5) G14(-9.5,16.5) G15(-8.5,16.5) G16(-7.5,16.5) G17(-6.5,16.5) G18(-5.5,16.5) G19(-4.5,16.5) G20(-3.5,16.5) G21(-2.5,16.5) G22(-1.5,16.5) G23(-0.5,16.5) G24(0.5,16.5) G25(1.5,16.5) G26(2.5,16.5) G27(3.5,16.5) G28(4.5,16.5) G29(5.5,16.5) G30(6.5,16.5) G31(7.5,16.5) G32(8.5,16.5) G33(9.5,16.5) G34(10.5,16.5) G35(11.5,16.5) G36(12.5,16.5) G37(13.5,16.5) G38(14.5,16.5) G39(15.5,16.5) G40(16.5,16.5) G41(17.5,16.5) G42(18.5,16.5) G43(19.5,16.5) G44(20.5,16.5) G45(21.5,16.5) G46(22.5,16.5) H1(-22.5,15.5) H2(-21.5,15.5) H3(-20.5,15.5) H4(-19.5,15.5) H5(-18.5,15.5) H6(-17.5,15.5) H7(-16.5,15.5) H8(-15.5,15.5) H9(-14.5,15.5) H10(-13.5,15.5) H11(-12.5,15.5) H12(-11.5,15.5) H13(-10.5,15.5) H14(-9.5,15.5) H15(-8.5,15.5) H16(-7.5,15.5) H17(-6.5,15.5) H18(-5.5,15.5) H19(-4.5,15.5) H20(-3.5,15.5) H21(-2.5,15.5) H22(-1.5,15.5) H23(-0.5,15.5) H24(0.5,15.5) H25(1.5,15.5) H26(2.5,15.5) H27(3.5,15.5) H28(4.5,15.5) H29(5.5,15.5) H30(6.5,15.5) H31(7.5,15.5) H32(8.5,15.5) H33(9.5,15.5) H34(10.5,15.5) H35(11.5,15.5) H36(12.5,15.5) H37(13.5,15.5) H38(14.5,15.5) H39(15.5,15.5) H40(16.5,15.5) H41(17.5,15.5) H42(18.5,15.5) H43(19.5,15.5) H44(20.5,15.5) H45(21.5,15.5) H46(22.5,15.5) J1(-22.5,14.5) J2(-21.5,14.5) J3(-20.5,14.5) J4(-19.5,14.5) J5(-18.5,14.5) J6(-17.5,14.5) J7(-16.5,14.5) J8(-15.5,14.5) J9(-14.5,14.5) J10(-13.5,14.5) J11(-12.5,14.5) J12(-11.5,14.5) J13(-10.5,14.5) J14(-9.5,14.5) J15(-8.5,14.5) J16(-7.5,14.5) J17(-6.5,14.5) J18(-5.5,14.5) J19(-4.5,14.5) J20(-3.5,14.5) J21(-2.5,14.5) J22(-1.5,14.5) J23(-0.5,14.5) J24(0.5,14.5) J25(1.5,14.5) J26(2.5,14.5) J27(3.5,14.5) J28(4.5,14.5) J29(5.5,14.5) J30(6.5,14.5) J31(7.5,14.5) J32(8.5,14.5) J33(9.5,14.5) J34(10.5,14.5) J35(11.5,14.5) J36(12.5,14.5) J37(13.5,14.5) J38(14.5,14.5) J39(15.5,14.5) J40(16.5,14.5) J41(17.5,14.5) J42(18.5,14.5) J43(19.5,14.5) J44(20.5,14.5) J45(21.5,14.5) J46(22.5,14.5) K1(-22.5,13.5) K2(-21.5,13.5) K3(-20.5,13.5) K4(-19.5,13.5) K5(-18.5,13.5) K6(-17.5,13.5) K7(-16.5,13.5) K8(-15.5,13.5) K9(-14.5,13.5) K10(-13.5,13.5) K11(-12.5,13.5) K12(-11.5,13.5) K13(-10.5,13.5) K14(-9.5,13.5) K15(-8.5,13.5) K16(-7.5,13.5) K17(-6.5,13.5) K18(-5.5,13.5) K19(-4.5,13.5) K20(-3.5,13.5) K21(-2.5,13.5) K22(-1.5,13.5) K23(-0.5,13.5) K24(0.5,13.5) K25(1.5,13.5) K26(2.5,13.5) K27(3.5,13.5) K28(4.5,13.5) K29(5.5,13.5) K30(6.5,13.5) K31(7.5,13.5) K32(8.5,13.5) K33(9.5,13.5) K34(10.5,13.5) K35(11.5,13.5) K36(12.5,13.5) K37(13.5,13.5) K38(14.5,13.5) K39(15.5,13.5) K40(16.5,13.5) K41(17.5,13.5) K42(18.5,13.5) K43(19.5,13.5) K44(20.5,13.5) K45(21.5,13.5) K46(22.5,13.5) L1(-22.5,12.5) L2(-21.5,12.5) L3(-20.5,12.5) L4(-19.5,12.5) L5(-18.5,12.5) L6(-17.5,12.5) L7(-16.5,12.5) L8(-15.5,12.5) L9(-14.5,12.5) L10(-13.5,12.5) L11(-12.5,12.5) L12(-11.5,12.5) L13(-10.5,12.5) L14(-9.5,12.5) L15(-8.5,12.5) L16(-7.5,12.5) L17(-6.5,12.5) L18(-5.5,12.5) L19(-4.5,12.5) L20(-3.5,12.5) L21(-2.5,12.5) L22(-1.5,12.5) L23(-0.5,12.5) L24(0.5,12.5) L25(1.5,12.5) L26(2.5,12.5) L27(3.5,12.5) L28(4.5,12.5) L29(5.5,12.5) L30(6.5,12.5) L31(7.5,12.5) L32(8.5,12.5) L33(9.5,12.5) L34(10.5,12.5) L35(11.5,12.5) L36(12.5,12.5) L37(13.5,12.5) L38(14.5,12.5) L39(15.5,12.5) L40(16.5,12.5) L41(17.5,12.5) L42(18.5,12.5) L43(19.5,12.5) L44(20.5,12.5) L45(21.5,12.5) L46(22.5,12.5) M1(-22.5,11.5) M2(-21.5,11.5) M3(-20.5,11.5) M4(-19.5,11.5) M5(-18.5,11.5) M6(-17.5,11.5) M7(-16.5,11.5) M8(-15.5,11.5) M9(-14.5,11.5) M10(-13.5,11.5) M11(-12.5,11.5) M12(-11.5,11.5) M13(-10.5,11.5) M14(-9.5,11.5) M15(-8.5,11.5) M16(-7.5,11.5) M17(-6.5,11.5) M18(-5.5,11.5) M19(-4.5,11.5) M20(-3.5,11.5) M21(-2.5,11.5) M22(-1.5,11.5) M23(-0.5,11.5) M24(0.5,11.5) M25(1.5,11.5) M26(2.5,11.5) M27(3.5,11.5) M28(4.5,11.5) M29(5.5,11.5) M30(6.5,11.5) M31(7.5,11.5) M32(8.5,11.5) M33(9.5,11.5) M34(10.5,11.5) M35(11.5,11.5) M36(12.5,11.5) M37(13.5,11.5) M38(14.5,11.5) M39(15.5,11.5) M40(16.5,11.5) M41(17.5,11.5) M42(18.5,11.5) M43(19.5,11.5) M44(20.5,11.5) M45(21.5,11.5) M46(22.5,11.5) N1(-22.5,10.5) N2(-21.5,10.5) N3(-20.5,10.5) N4(-19.5,10.5) N5(-18.5,10.5) N6(-17.5,10.5) N7(-16.5,10.5) N8(-15.5,10.5) N9(-14.5,10.5) N10(-13.5,10.5) N11(-12.5,10.5) N12(-11.5,10.5) N13(-10.5,10.5) N14(-9.5,10.5) N15(-8.5,10.5) N16(-7.5,10.5) N17(-6.5,10.5) N18(-5.5,10.5) N19(-4.5,10.5) N20(-3.5,10.5) N21(-2.5,10.5) N22(-1.5,10.5) N23(-0.5,10.5) N24(0.5,10.5) N25(1.5,10.5) N26(2.5,10.5) N27(3.5,10.5) N28(4.5,10.5) N29(5.5,10.5) N30(6.5,10.5) N31(7.5,10.5) N32(8.5,10.5) N33(9.5,10.5) N34(10.5,10.5) N35(11.5,10.5) N36(12.5,10.5) N37(13.5,10.5) N38(14.5,10.5) N39(15.5,10.5) N40(16.5,10.5) N41(17.5,10.5) N42(18.5,10.5) N43(19.5,10.5) N44(20.5,10.5) N45(21.5,10.5) N46(22.5,10.5) P1(-22.5,9.5) P2(-21.5,9.5) P3(-20.5,9.5) P4(-19.5,9.5) P5(-18.5,9.5) P6(-17.5,9.5) P7(-16.5,9.5) P8(-15.5,9.5) P9(-14.5,9.5) P10(-13.5,9.5) P11(-12.5,9.5) P12(-11.5,9.5) P13(-10.5,9.5) P14(-9.5,9.5) P15(-8.5,9.5) P16(-7.5,9.5) P17(-6.5,9.5) P18(-5.5,9.5) P19(-4.5,9.5) P20(-3.5,9.5) P21(-2.5,9.5) P22(-1.5,9.5) P23(-0.5,9.5) P24(0.5,9.5) P25(1.5,9.5) P26(2.5,9.5) P27(3.5,9.5) P28(4.5,9.5) P29(5.5,9.5) P30(6.5,9.5) P31(7.5,9.5) P32(8.5,9.5) P33(9.5,9.5) P34(10.5,9.5) P35(11.5,9.5) P36(12.5,9.5) P37(13.5,9.5) P38(14.5,9.5) P39(15.5,9.5) P40(16.5,9.5) P41(17.5,9.5) P42(18.5,9.5) P43(19.5,9.5) P44(20.5,9.5) P45(21.5,9.5) P46(22.5,9.5) R1(-22.5,8.5) R2(-21.5,8.5) R3(-20.5,8.5) R4(-19.5,8.5) R5(-18.5,8.5) R6(-17.5,8.5) R7(-16.5,8.5) R8(-15.5,8.5) R9(-14.5,8.5) R10(-13.5,8.5) R11(-12.5,8.5) R12(-11.5,8.5) R13(-10.5,8.5) R14(-9.5,8.5) R15(-8.5,8.5) R16(-7.5,8.5) R17(-6.5,8.5) R18(-5.5,8.5) R19(-4.5,8.5) R20(-3.5,8.5) R21(-2.5,8.5) R22(-1.5,8.5) R23(-0.5,8.5) R24(0.5,8.5) R25(1.5,8.5) R26(2.5,8.5) R27(3.5,8.5) R28(4.5,8.5) R29(5.5,8.5) R30(6.5,8.5) R31(7.5,8.5) R32(8.5,8.5) R33(9.5,8.5) R34(10.5,8.5) R35(11.5,8.5) R36(12.5,8.5) R37(13.5,8.5) R38(14.5,8.5) R39(15.5,8.5) R40(16.5,8.5) R41(17.5,8.5) R42(18.5,8.5) R43(19.5,8.5) R44(20.5,8.5) R45(21.5,8.5) R46(22.5,8.5) T1(-22.5,7.5) T2(-21.5,7.5) T3(-20.5,7.5) T4(-19.5,7.5) T5(-18.5,7.5) T6(-17.5,7.5) T7(-16.5,7.5) T8(-15.5,7.5) T9(-14.5,7.5) T10(-13.5,7.5) T11(-12.5,7.5) T12(-11.5,7.5) T13(-10.5,7.5) T14(-9.5,7.5) T15(-8.5,7.5) T16(-7.5,7.5) T17(-6.5,7.5) T18(-5.5,7.5) T19(-4.5,7.5) T20(-3.5,7.5) T21(-2.5,7.5) T22(-1.5,7.5) T23(-0.5,7.5) T24(0.5,7.5) T25(1.5,7.5) T26(2.5,7.5) T27(3.5,7.5) T28(4.5,7.5) T29(5.5,7.5) T30(6.5,7.5) T31(7.5,7.5) T32(8.5,7.5) T33(9.5,7.5) T34(10.5,7.5) T35(11.5,7.5) T36(12.5,7.5) T37(13.5,7.5) T38(14.5,7.5) T39(15.5,7.5) T40(16.5,7.5) T41(17.5,7.5) T42(18.5,7.5) T43(19.5,7.5) T44(20.5,7.5) T45(21.5,7.5) T46(22.5,7.5) U1(-22.5,6.5) U2(-21.5,6.5) U3(-20.5,6.5) U4(-19.5,6.5) U5(-18.5,6.5) U6(-17.5,6.5) U7(-16.5,6.5) U8(-15.5,6.5) U9(-14.5,6.5) U10(-13.5,6.5) U11(-12.5,6.5) U12(-11.5,6.5) U13(-10.5,6.5) U14(-9.5,6.5) U15(-8.5,6.5) U16(-7.5,6.5) U17(-6.5,6.5) U18(-5.5,6.5) U19(-4.5,6.5) U20(-3.5,6.5) U21(-2.5,6.5) U22(-1.5,6.5) U23(-0.5,6.5) U24(0.5,6.5) U25(1.5,6.5) U26(2.5,6.5) U27(3.5,6.5) U28(4.5,6.5) U29(5.5,6.5) U30(6.5,6.5) U31(7.5,6.5) U32(8.5,6.5) U33(9.5,6.5) U34(10.5,6.5) U35(11.5,6.5) U36(12.5,6.5) U37(13.5,6.5) U38(14.5,6.5) U39(15.5,6.5) U40(16.5,6.5) U41(17.5,6.5) U42(18.5,6.5) U43(19.5,6.5) U44(20.5,6.5) U45(21.5,6.5) U46(22.5,6.5) V1(-22.5,5.5) V2(-21.5,5.5) V3(-20.5,5.5) V4(-19.5,5.5) V5(-18.5,5.5) V6(-17.5,5.5) V7(-16.5,5.5) V8(-15.5,5.5) V9(-14.5,5.5) V10(-13.5,5.5) V11(-12.5,5.5) V12(-11.5,5.5) V13(-10.5,5.5) V14(-9.5,5.5) V15(-8.5,5.5) V16(-7.5,5.5) V17(-6.5,5.5) V18(-5.5,5.5) V19(-4.5,5.5) V20(-3.5,5.5) V21(-2.5,5.5) V22(-1.5,5.5) V23(-0.5,5.5) V24(0.5,5.5) V25(1.5,5.5) V26(2.5,5.5) V27(3.5,5.5) V28(4.5,5.5) V29(5.5,5.5) V30(6.5,5.5) V31(7.5,5.5) V32(8.5,5.5) V33(9.5,5.5) V34(10.5,5.5) V35(11.5,5.5) V36(12.5,5.5) V37(13.5,5.5) V38(14.5,5.5) V39(15.5,5.5) V40(16.5,5.5) V41(17.5,5.5) V42(18.5,5.5) V43(19.5,5.5) V44(20.5,5.5) V45(21.5,5.5) V46(22.5,5.5) W1(-22.5,4.5) W2(-21.5,4.5) W3(-20.5,4.5) W4(-19.5,4.5) W5(-18.5,4.5) W6(-17.5,4.5) W7(-16.5,4.5) W8(-15.5,4.5) W9(-14.5,4.5) W10(-13.5,4.5) W11(-12.5,4.5) W12(-11.5,4.5) W13(-10.5,4.5) W14(-9.5,4.5) W15(-8.5,4.5) W16(-7.5,4.5) W17(-6.5,4.5) W18(-5.5,4.5) W19(-4.5,4.5) W20(-3.5,4.5) W21(-2.5,4.5) W22(-1.5,4.5) W23(-0.5,4.5) W24(0.5,4.5) W25(1.5,4.5) W26(2.5,4.5) W27(3.5,4.5) W28(4.5,4.5) W29(5.5,4.5) W30(6.5,4.5) W31(7.5,4.5) W32(8.5,4.5) W33(9.5,4.5) W34(10.5,4.5) W35(11.5,4.5) W36(12.5,4.5) W37(13.5,4.5) W38(14.5,4.5) W39(15.5,4.5) W40(16.5,4.5) W41(17.5,4.5) W42(18.5,4.5) W43(19.5,4.5) W44(20.5,4.5) W45(21.5,4.5) W46(22.5,4.5) Y1(-22.5,3.5) Y2(-21.5,3.5) Y3(-20.5,3.5) Y4(-19.5,3.5) Y5(-18.5,3.5) Y6(-17.5,3.5) Y7(-16.5,3.5) Y8(-15.5,3.5) Y9(-14.5,3.5) Y10(-13.5,3.5) Y11(-12.5,3.5) Y12(-11.5,3.5) Y13(-10.5,3.5) Y14(-9.5,3.5) Y15(-8.5,3.5) Y16(-7.5,3.5) Y17(-6.5,3.5) Y18(-5.5,3.5) Y19(-4.5,3.5) Y20(-3.5,3.5) Y21(-2.5,3.5) Y22(-1.5,3.5) Y23(-0.5,3.5) Y24(0.5,3.5) Y25(1.5,3.5) Y26(2.5,3.5) Y27(3.5,3.5) Y28(4.5,3.5) Y29(5.5,3.5) Y30(6.5,3.5) Y31(7.5,3.5) Y32(8.5,3.5) Y33(9.5,3.5) Y34(10.5,3.5) Y35(11.5,3.5) Y36(12.5,3.5) Y37(13.5,3.5) Y38(14.5,3.5) Y39(15.5,3.5) Y40(16.5,3.5) Y41(17.5,3.5) Y42(18.5,3.5) Y43(19.5,3.5) Y44(20.5,3.5) Y45(21.5,3.5) Y46(22.5,3.5)
Top Overlay:
  circle w0.25: c-24.4,22.5 r0.125
  region: -22.75,23.75 -23.75,22.75 -23.75,23.75
  lines w0.2: -23.75,22.75 -22.75,23.75 ; -23.75,-23.75 -23.75,23.75 23.75,23.75 23.75,-23.75 -23.75,-23.75
Mechanical 13:
  lines w0.1: -23.75,-23.75 -23.75,23.75 23.75,23.75 23.75,-23.75 -23.75,-23.75
Mechanical 15:
  lines w0.1: -0.5,0 0.5,0 ; 0,-0.5 0,0.5 ; -24.75,-24.75 -24.75,24.75 24.75,24.75 24.75,-24.75 -24.75,-24.75
3D body: height 0, standoff 0, extent -23.75,-23.75 23.75,23.75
